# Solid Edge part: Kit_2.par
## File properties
Sűrűség: 0,000 kg/m^3
Pontosság: 0,990
Author: ahadarics
Last saved by: psaghy
Revision: 78
Username: ahadarics
Dokumentum tartalom típus: 0
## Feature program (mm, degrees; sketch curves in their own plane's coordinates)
base feature "unnamed BaseFeature 1"
sketch for "Furat_1" plane through (0, -3, 8.5) normal (0, 0, 1) x-axis (0, 1, 0)
  hole centre (-0.5, 0) bore radius 2.067
hole "Furat_1" nominal diameter 5 finite  ThreadDepth = 4.5 mm
chamfer "Letörés_1" setback 0.5
sketch for "Kihúzás_2" #1 plane through (0, 19.5, 0) normal (0, 1, 0) x-axis (0, 0, -1)
  arc centre (0, 0) radius 8 from (5.2915, -6) to (-5.2915, -6) cw
  line (-5.2915, -6) -> (5.2915, -6)
sketch for "Kihúzás_2" #2 plane through (0, 19.5, 0) normal (0, 1, 0) x-axis (0, 0, -1)
  line (-5.2915, 6) -> (5.2915, 6)
extrude "Kihúzás_2" add finite 13.84 along -normal
thread "unnamed Thread 1"
sketch for "Kivágás_1" #1 plane through (0, 19.5, 0) normal (0, 1, 0) x-axis (0, 0, -1)
  line (-5.2915, -6) -> (5.2915, -6)
  arc centre (0, 0) radius 8 from (5.2915, -6) to (-5.2915, -6) cw
sketch for "Kivágás_1" #2 plane through (0, 19.5, 0) normal (0, 1, 0) x-axis (0, 0, -1)
  line (-5.2915, 6) -> (5.2915, 6)
extrude "Kivágás_1" cut finite 13.85 along -normal
chamfer "Letörés_2" setback 1
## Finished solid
Body 1: solid body, 32 faces, 71 edges, 40 vertices.
  Faces by surface: plane 13, cylinder 11, cone 8
  Edges by curve: line 32, circle 31, intersection 4, spline 4
Bounding box of the edges (mm): 19.000 x 28.500 x 18.000, from (-9.5, -9, -9.5) to (9.5, 19.5, 8.5).
Cylindrical faces by radius (mm): R2.055 x1, R2.067 x1, R3 x1, R6.6 x1, R6.85 x2, R8 x4, R9.5 x1
Conical faces (half-angle, radius in mm at the cone's reference point): 45 deg R2.567 x1, 45 deg R3.1 x2, 45 deg R8 x2, 59 deg R1.0335 x1, 60 deg R7.425 x2
Planar faces by outward normal: +x 1, +y 7, +z 2, -x 1, -y 2
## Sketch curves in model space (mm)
arc centre (0, 19.5, 0) radius 8 from (6, 19.5, -5.2915) through (7.9967, 19.5, 0.2312) to (6, 19.5, 5.2915)
line (6, 19.5, 5.2915) -> (6, 19.5, -5.2915)
arc centre (0, 19.5, 0) radius 8 from (-6, 19.5, 5.2915) through (-7.9967, 19.5, -0.2312) to (-6, 19.5, -5.2915)
line (-6, 19.5, 5.2915) -> (-6, 19.5, -5.2915)
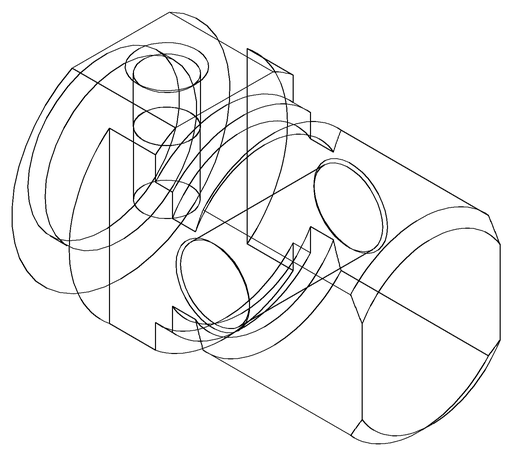
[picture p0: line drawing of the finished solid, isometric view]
